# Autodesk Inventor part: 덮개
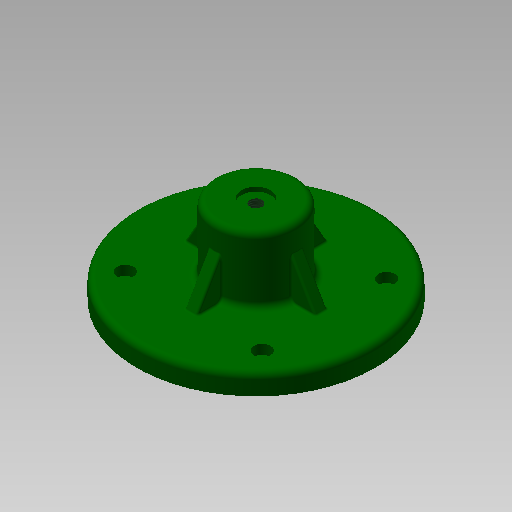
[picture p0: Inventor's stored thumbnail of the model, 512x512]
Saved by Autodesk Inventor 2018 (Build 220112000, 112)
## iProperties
Created: 2017-08
Part Number: 덮개
Material: 알루미늄 6061
Document SubType Name: Modeling
Designer: mduedu
Density: 2.71 g/cm^3
Mass: 358.12 g
Surface Area: 294.002 cm^2
Volume: 132.148 cm^3
Appearance: 알루미늄 - 평지
Author: mduedu
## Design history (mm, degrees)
sketch "스케치1"
  geometry: C1 r 57.5 at (0, 0); 1 further point
  constraints: 1 centre point, 1 coincident
  dimensions: "d69" = 115 diameter of C1
extrude "돌출1" new body sketch "스케치1" distance "d5" = 10; taper "d6" = 0 deg
sketch "스케치2"
  geometry: C1 r 20 at (0, 0); 1 further point
  constraints: 1 centre point, 1 coincident
  dimensions: "d55" = 40 diameter of C1
extrude "돌출2" join sketch "스케치2" distance "d9" = 32; taper "d10" = 0 deg
sketch "스케치3"
  geometry: L1 (-26, -26)-(26, -26); L2 (26, -26)-(26, 26); L3 (26, 26)-(-26, 26); L4 (-26, 26)-(-26, -26); L5 (-26, -26)-(26, 26); L6 (26, -26)-(-26, 26); 1 further point
  constraints: 12 end point, 2 midpoint, 2 parallel, 2 perpendicular, 1 horizontal
  dimensions: "d11" = 52 distance of L3.end L2.end
extrude "돌출3" join sketch "스케치3" distance "d12" = 6; taper "d13" = 0 deg
sketch "스케치4"
  geometry: L1 (-17, -17)-(17, -17); L2 (17, -17)-(17, 17); L3 (17, 17)-(-17, 17); L4 (-17, 17)-(-17, -17); L5 (-17, -17)-(17, 17); L6 (17, -17)-(-17, 17); 1 further point
  constraints: 12 end point, 2 midpoint, 2 parallel, 2 perpendicular, 1 horizontal
  dimensions: "d14" = 34 distance of L2.end L3.end
extrude "돌출4" cut sketch "스케치4" distance "d16" = 5; taper "d17" = 0 deg
sketch "스케치5"
  geometry: C1 r 9 at (0, 0); 1 further point
  constraints: 1 centre point, 1 coincident
  dimensions: "d18" = 18 diameter of C1
extrude "돌출5" cut sketch "스케치5" distance "d19" = 34; taper "d20" = 0 deg
sketch "스케치6"
  geometry: 2 further points
  constraints: 1 coincident
hole "구멍1" sketch "스케치6" at (0, 0) diameter "d21" = 5.917; stored, may be unused: countersink angle "d25" = 90 deg, drill point angle "d27" = 118 deg; dims "d22" = 6, "d23" = 14, "d24" = 2, "d26" = 8
fillet "모깎기3" dims "d38" = 3
fillet "모깎기4" dims "d39" = 3
fillet "모깎기5" dims "d40" = 3
chamfer "모따기2" distance "d70" = 6; stored, may be unused: second distance "d71" = 2, angle "d72" = 45 deg
chamfer "모따기1" distance "d41" = 1; stored, may be unused: second distance "d42" = 2, angle "d43" = 45 deg
fillet "모깎기6" dims "d44" = 3
fillet "모깎기7" dims "d45" = 3
fillet "모깎기8" dims "d46" = 3
sketch "스케치9"
  geometry: L1 (-33, -30)-(33, -30); L2 (33, -30)-(33, 30); L3 (33, 30)-(-33, 30); L4 (-33, 30)-(-33, -30); L5 (-33, -30)-(33, 30); L6 (33, -30)-(-33, 30); C1 r 54.5 at (0, 0) reference; 3 further points
  constraints: 12 end point, 2 coincident, 2 midpoint, 2 parallel, 2 point on line, 1 horizontal, 1 perpendicular
  dimensions: "d77" = 66 distance of L2.end L3.end; "d79" = 60 distance of L1.end L2.end
hole "구멍3" sketch "스케치9" at (-33, -30), (-33, 30), (33, 30), (33, -30) diameter "d48" = 4.5; stored, may be unused: countersink angle "d52" = 90 deg, drill point angle "d54" = 0 deg; dims "d49" = 6, "d50" = 8, "d51" = 4.6, "d53" = 8
sketch "스케치10"
  geometry: L1 (-7, 40)-(-2.958, 40) reference; L2 (-2.958, 40)-(-2.958, 33) reference; L3 (-2.958, 33)-(-6, 33) reference; L4 (-9, 30)-(-9, -1) reference; L5 (-9, -1)-(-14, -1) reference; L6 (-17, -4)-(-17, -6) reference; L7 (-17, -6)-(-25, -6) reference; L8 (-25, -6)-(-26, -5) reference; L9 (-26, -5)-(-26, 0) reference; L10 (-26, 0)-(-57.5, 0) reference; L11 (-54.5, 10)-(-23, 10) reference; L12 (-20, 13)-(-20, 39) reference; L13 (-17, 42)-(-7, 42) reference; L14 (-7, 42)-(-7, 40) reference; L15 (2.958, 40)-(7, 40) reference; L16 (7, 40)-(7, 42) reference; L17 (7, 42)-(17, 42) reference; L18 (20, 39)-(20, 13) reference; L19 (23, 10)-(54.5, 10) reference; L20 (57.5, 0)-(26, 0) reference; L21 (26, 0)-(26, -5) reference; L22 (26, -5)-(25, -6) reference; L23 (25, -6)-(17, -6) reference; L24 (17, -6)-(17, -4) reference; L25 (14, -1)-(9, -1) reference; L26 (9, -1)-(9, 30) reference; L27 (6, 33)-(2.958, 33) reference; L28 (2.958, 33)-(2.958, 40) reference; L29 (31.547, 10)-(20, 30); L30 (-57.5, 0)-(-57.5, 7) reference; L31 (57.5, 7)-(57.5, 0) reference; A1 r 3 centre (-6, 30) between (-6, 33) and (-9, 30) reference; A2 r 3 centre (-14, -4) between (-14, -1) and (-17, -4) reference; A3 r 3 centre (-23, 13) between (-23, 10) and (-20, 13) reference; A4 r 3 centre (-17, 39) between (-17, 42) and (-20, 39) reference; A5 r 3 centre (17, 39) between (20, 39) and (17, 42) reference; A6 r 3 centre (23, 13) between (20, 13) and (23, 10) reference; A7 r 3 centre (14, -4) between (17, -4) and (14, -1) reference; A8 r 3 centre (6, 30) between (9, 30) and (6, 33) reference; A9 r 3 centre (-54.5, 7) between (-54.5, 10) and (-57.5, 7) reference; 2 further points
  constraints: 2 end point, 2 point on line, 1 other
  dimensions: "d56" = 20 distance from line of L29.end L19; "d57" = 120 deg angle of L29 L19
feature "리브1" sketch "스케치10" dims "d58" = 1, "d59" = 6, "d60" = 0, "d61" = 0, "d62" = 1, "d63" = 1
fillet "모깎기9" dims "d64" = 1
fillet "모깎기10" dims "d65" = 1
node "솔리드1"
pattern_circular "원형 패턴1" dims angle "d67" = 360 deg
node "절단 모서리 투영1"
